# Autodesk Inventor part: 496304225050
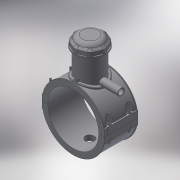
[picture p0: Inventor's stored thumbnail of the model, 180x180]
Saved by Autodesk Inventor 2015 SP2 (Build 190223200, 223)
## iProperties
Created: 2017-07
Part Number: 496304225050
Material: Generic
Description: PLASSON TAPPING SADDLE 225x50
Document SubType Name: Modeling
Designer: KIM
Mass: 1628.43 g
Surface Area: 3500.81 cm^2
Volume: 1628.43 cm^3
Density: 1 g/cm^3
Appearance: Default
Author: KIM
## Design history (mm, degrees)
derived "496304.ipt"
feature "Solid1::496304.ipt"
feature "Solid2::496304.ipt"
feature "Solid4::496304.ipt"
feature "Solid5::496304.ipt"
tag "TaggingFeature1" dims "B_" = 227
body "Solid1"
body "Solid2"
other parameters: "d_" = 225, "L_" = 176, "d_t" = 6, "H_2" = 177, "H_1" = 64, "H_" = 123, "d1" = 256.5, "d148" = 3.375, "d160" = 3.375, "d169" = 3.375, "d192" = 6.3, "d0" = 225, "d2" = 295.1, "d3" = 56.25, "d4" = 176, "d5" = 0, "d6" = 0.1, "d8" = 0, "d19" = 6, "d20" = 6, "d21" = 105.6, "d23" = 0, "d24" = 52.8, "d26" = 0, "d29" = 3, "d30" = 75, "d31" = 6, "d32" = 0, "d33" = 0, "d34" = 0.6, "d40" = 133.38, "d43" = 0, "d45" = 0, "d47" = 233.85, "d70" = 15, "d72" = 0, "d73" = 6, "d75" = 5, "d76" = 0, "d77" = 11.25, "d78" = 142.5, "d79" = 15, "d80" = 70.4, "d82" = 5 deg, "d84" = 4, "d85" = 14, "d86" = 0, "d87" = 3, "d88" = 0, "d89" = 1, "d90" = 1, "d91" = 140.8, "d92" = 0, "d93" = 0.5, "d94" = 118.42105, "d96" = 261.63, "d97" = 3.52, "d98" = 0, "d102" = 2.25, "d120" = 140 deg, "d121" = 24.228, "d122" = 20 deg, "d123" = 513, "d124" = 153.9, "d126" = 0, "d143" = 231.75, "d145" = 24.23077, "d149" = 3.375, "d150" = 26.65385, "d153" = 176, "d154" = 0, "d156" = 128.25, "d157" = 160 deg, "d159" = 6.3, "d161" = 3.375, "d162" = 105.6, "d163" = 0, "d164" = 112.5, "d167" = 22.5, "d168" = 125.12195, "d170" = 3.375, "d172" = 0, "d173" = 1, "d175" = 112.5, "d176" = 20 deg, "d177" = 15.75, "d178" = 31.5, "d180" = 0, "d183" = 12.6, "d184" = 12.6, "d185" = 57.2, "d186" = 57.2, "d187" = 128.25, "d188" = 9.45, "d189" = 15.75, "d190" = 0, "d191" = 192.375, "d193" = 6.3, "d194" = 6.16, "d195" = 90 deg, "d197" = 0, "d199" = 0, "d200" = 15.75, "d202" = 0, "d203" = 177, "d204" = 85.5, "d205" = 63, "d206" = 76.5, "d207" = 132.75, "d208" = 138.06, "d209" = 164.61, "d210" = 77.4, "d212" = 72, "d213" = 35.1, "d216" = 0, "d217" = 22.5, "d218" = 22.5, "d219" = 4.5, "d222" = 225, "d224" = 0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
